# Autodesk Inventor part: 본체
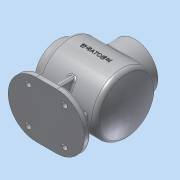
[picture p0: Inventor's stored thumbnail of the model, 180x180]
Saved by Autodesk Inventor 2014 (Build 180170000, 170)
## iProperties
Created: 2023-01
Part Number: 본체
Material: 알루미늄 6061
Document SubType Name: Modeling
Designer: dg
Density: 2.71 g/cm^3
Appearance: 알루미늄 - 평지
Mass: 1038.22 g
Surface Area: 1157.5 cm^2
Volume: 383.109 cm^3
Author: dg
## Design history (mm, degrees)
sketch "스케치1"
  geometry: L1 (-61, 0)-(61, 0); L2 (50.087, 50)-(-49, 50); L3 (-49, 50)-(-49, 38); L4 (-49, 38)-(-61, 38); L5 (-61, 38)-(-61, 0); L6 (-44, 27)-(-44, 45); L7 (-44, 45)-(46.83, 45); L8 (-61, 27)-(-44, 27); A1 r 120 centre (-59, 0) between (61, 0) and (50.087, 50); A2 r 115 centre (-59, 0) between (56, 0) and (46.83, 45); 2 further points
  constraints: 16 end point, 4 point on circle, 3 point on line, 2 centre point, 2 horizontal, 2 parallel, 2 perpendicular, 1 coincident, 1 midpoint, 1 vertical
  dimensions: "d0" = 122 distance of L1.start L1.end; "d1" = 120 radius of A1; "d2" = 100 diameter of L2 L1; "d3" = 76 diameter of L4 L1; "d5" = 5 radial gap between concentric circles of A1 A2; "d6" = 5 distance between parallel lines of L2 L7; "d8" = 54 diameter of L8 L1; "d9" = 17 distance of L8.start L6.start; "d98" = 110 distance from line of L1.end L3
revolve "회전1" sketch "스케치1" stored, may be unused: angle "d10" = 90 deg
fillet "모깎기1" dims "d11" = 8
node "작업 평면1"
sketch "스케치2"
  geometry: L1 (-17, 0)-(17, 0); L2 (-17, -46)-(17, -46); L3 (17, 46)-(-17, 46); A1 r 46 centre (-17, 0) between (-17, 46) and (-17, -46); A2 r 46 centre (17, 0) between (17, -46) and (17, 46); 2 further points
  constraints: 8 end point, 4 point on circle, 4 tangent, 2 centre point, 1 coincident, 1 horizontal, 1 midpoint, 1 parallel
  dimensions: "d14" = 92 distance between parallel lines of L2 L3; "d15" = 126 dimension on A2 A1
extrude "돌출1" join sketch "스케치2" distance "d23" = 10; taper "d24" = 0 deg
node "작업 평면3"
sketch "스케치3"
  geometry: L1 (49, 42)-(49, -42) reference; L2 (-52.243, -45)-(-52.243, 45) reference; L3 (61, 38)-(61, -38) reference; C1 r 38 at (-2, 0); A1 r 120 centre (59, 0) between (-52.243, 45) and (-52.243, -45) reference; 1 further point
  constraints: 1 centre point, 1 horizontal alignment, 1 midpoint
  dimensions: "d26" = 76 diameter of C1; "d97" = 63 distance from line of L3 C1.centre
extrude "돌출2" join sketch "스케치3" stored distance "d27" = 10; taper "d28" = 0 deg
hole "구멍1" diameter "d31" = 54; stored, may be unused: countersink angle "d35" = 90 deg, drill point angle "d37" = 118 deg; dims "d29" = 10, "d30" = 10, "d32" = 6, "d33" = 4, "d34" = 2, "d36" = 53.5
sketch "스케치4"
  geometry: L1 (-5, 35)-(5, 35); L2 (5, 35)-(5, -35); L3 (5, -35)-(-5, -35); L4 (-5, -35)-(-5, 35); 3 further points
  constraints: 8 end point, 2 midpoint, 2 parallel, 1 horizontal, 1 horizontal alignment, 1 perpendicular, 1 vertical alignment
  dimensions: "d38" = 10 distance of L1.start L1.end; "d39" = 70 distance of L3.end L1.start
extrude "돌출3" join sketch "스케치4" stored distance "d40" = 10; taper "d41" = 0 deg
sketch "스케치5"
  geometry: L1 (-5, -70)-(-5, -35.707) reference; L2 (-41, -50)-(44.827, -50) reference; L3 (-41, -50)-(44.827, -50) reference; L4 (5, -70)-(5, -35.707) reference; L5 (-34.641, -50)-(-40, -70); L6 (-17, -70)-(-63, -70) reference; L7 (46.83, -45)-(-44, -45) reference; L8 (17, -80)-(-17, -80) reference; L9 (0, -45)-(0, -80); 1 further point
  constraints: 4 end point, 2 midpoint, 2 point on line
  dimensions: "d42" = 105 deg angle of L6 L5; "d43" = 40 distance from line of L9 L5.end; "d44" = 23 distance of L6.end L5.end
feature "리브1" sketch "스케치5" dims "d45" = 1, "d46" = 10, "d47" = 0, "d48" = 0, "d49" = 1, "d50" = 1
fillet "모깎기2" dims "d51" = 3
fillet "모깎기3" dims "d52" = 3
fillet "모깎기4" dims "d53" = 3
sketch "스케치6"
  geometry: C1 r 4.5 at (-30, 30); C2 r 4.5 at (30, 30); C3 r 4.5 at (30, -30); C4 r 4.5 at (-30, -30); 1 further point
  constraints: 4 centre point, 3 equal radius, 2 vertical alignment
  dimensions: "d54" = 30 horizontal distance of point (0, 0) C1.centre; "d55" = 60 distance of C4.centre C1.centre; "d56" = 30 horizontal distance of point (0, 0) C1.centre; "d57" = 30 horizontal distance of point (0, 0) C2.centre; "d58" = 30 horizontal distance of point (0, 0) C2.centre; "d59" = 30 horizontal distance of C3.centre point (0, 0); "d60" = 9 diameter of C1
extrude "돌출4" cut sketch "스케치6" distance "d61" = 10; taper "d62" = 0 deg
chamfer "모따기1" distance "d63" = 1; stored, may be unused: second distance "d64" = 2, angle "d65" = 45 deg
sketch "스케치7"
  geometry: C1 r 38 at (0, 0) reference; 1 further point
  constraints: 1 vertical alignment
  dimensions: "d66" = 32.5 distance of C1.centre point (0, 32.5)
hole "구멍2" sketch "스케치7" at (0, 32.5) diameter "d67" = 3.242; stored, may be unused: countersink angle "d71" = 82 deg, drill point angle "d73" = 118 deg; dims "d68" = 8, "d69" = 3.023, "d70" = 2, "d72" = 10
sketch "스케치8"
  geometry: C1 r 38 at (0, 0) reference; 1 further point
  constraints: 1 vertical alignment
  dimensions: "d77" = 32.5 distance of point (0, 32.5) C1.centre
hole "구멍3" sketch "스케치8" at (0, 32.5) diameter "d78" = 3.242; stored, may be unused: countersink angle "d82" = 82 deg, drill point angle "d84" = 118 deg; dims "d79" = 8, "d80" = 3.023, "d81" = 2, "d83" = 10
fillet "모깎기5" dims "d88" = 3
node "작업 평면4"
sketch "스케치10"
  geometry: L1 (-61.544, -38)-(-61.544, 38) reference; L2 (62.456, -80)-(16.456, -80) reference; 2 further points
  constraints: 1 other
  dimensions: "d89" = 63 distance from line of L1 point (1.456, 0); "d90" = 80 distance from line of L2 point (1.456, 0)
feature "엠보싱1" sketch "스케치10" dims "d0" = 122, "d1" = 120, "d2" = 100, "d3" = 76, "d5" = 5, "d6" = 5, "d8" = 54, "d9" = 17, "d14" = 92, "d15" = 126, "d91" = 0.5, "d92" = 0, "d98" = 110
fillet "모깎기6" dims "d94" = 3
node "솔리드1"
mirror "대칭1"
pattern_circular "원형 패턴1" dims angle "d75" = 360 deg
pattern_circular "원형 패턴2" dims angle "d86" = 360 deg
node "투영된 루프1"
other parameters: "d25" = 144
